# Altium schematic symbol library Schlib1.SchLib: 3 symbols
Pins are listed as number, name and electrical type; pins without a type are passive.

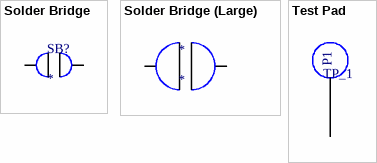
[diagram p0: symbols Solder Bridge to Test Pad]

## Solder Bridge
designator SB?
footprint Solder Bridge
pins: 1, 2

## Solder Bridge (Large)
designator *
footprint Solder Bridge (Large)
pins: 1, 2

## Test Pad
designator TP_1, comment TP_1  (no BOM)
footprint Test Pad
pins: 4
